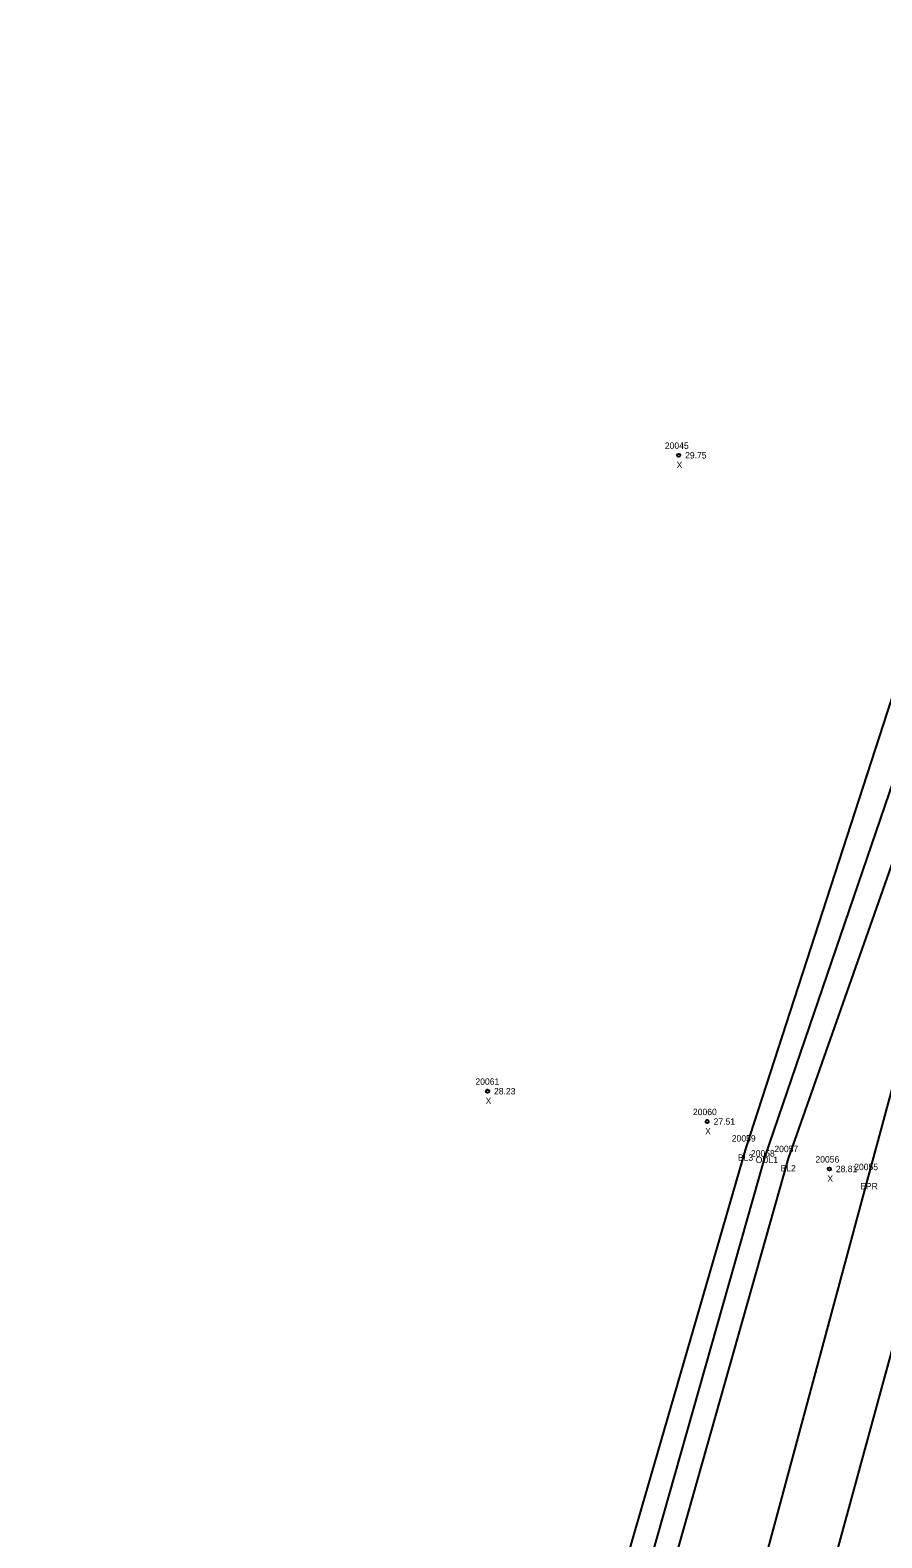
# Model space of a CAD drawing. Extents: x 2432729 to 2433340, y 684958 to 688103.
# Drawn here: x 2432891.8 to 2433024.5, y 687632.9 to 687867.9 of the extents above; entities that cross this region are included whole.
import ezdxf

# ---------------------------------------------------------------- set-up
doc = ezdxf.new("R2010")
doc.units = 0
for name, color, linetype in [('RD_DTM_BkLn1', 7, 'Continuous'), ('RD_EX_H2O', 7, 'Continuous'), ('RD_EX_H2O_txCode', 7, 'Continuous'), ('RD_EX_Road', 7, 'Continuous'), ('RD_EX_Road_txCode', 7, 'Continuous'), ('RD_Sketch8', 7, 'Continuous'), ('RD_SMD_Locator', 7, 'Continuous'), ('RD_SMD_Misc', 7, 'Continuous')]:
    doc.layers.add(name, color=color, linetype=linetype)

msp = doc.modelspace()

# ---------------------------------------------------------------- linework, layer by layer
at = {"layer": 'RD_DTM_BkLn1'}
for points in [[(2433118.26, 688093.2), (2433092.06, 687992.21), (2433063.59, 687892.57), (2433035.4, 687792.67), (2433003.26, 687693.63), (2432973.78, 687591.87), (2432942.45, 687477.63), (2432922.14, 687395), (2432910.39, 687336.67), (2432899.1, 687275.13), (2432892.65, 687218), (2432891.75, 687172.49)], [(2433125.46, 688091.48), (2433098.1, 687989.98), (2433070.67, 687890.07), (2433044.57, 687790.6), (2433009.89, 687691.98), (2432980.82, 687589.28), (2432951.34, 687483.95), (2432927.37, 687394.4), (2432914.6, 687336.1), (2432907.58, 687275.27), (2432904.68, 687217.27), (2432900.37, 687172.96), (2432891.75, 687172.49)], [(2433140.82, 688087.65), (2433112.94, 687984.39), (2433086.23, 687884.97), (2433060.15, 687787.81), (2433032.83, 687687.07), (2433004.93, 687584.9), (2432976.21, 687475.71), (2432953.67, 687387.58), (2432941.78, 687332.31), (2432932.37, 687274.14), (2432926.02, 687213.66), (2432924.35, 687158.94)]]:
    msp.add_lwpolyline(points, dxfattribs=at)
at = {"layer": 'RD_EX_H2O'}
msp.add_lwpolyline([(2433122.48, 688092.22), (2433094.03, 687991.07), (2433066.93, 687892.02), (2433040.1, 687791.41), (2433006.23, 687692.29), (2432977.32, 687590.19), (2432946.52, 687480.52), (2432925.1, 687394.47), (2432912.11, 687336.21), (2432903.51, 687275.66), (2432898.99, 687217.48), (2432895.84, 687179.01)], dxfattribs=at)
at = {"layer": 'RD_EX_Road'}
msp.add_lwpolyline([(2433130.63, 688090.22), (2433103.18, 687988.73), (2433075.68, 687887.89), (2433049.83, 687790.75), (2433022.33, 687689.17), (2432994.76, 687586.82), (2432966.23, 687480.17), (2432943.15, 687390.42), (2432931.4, 687334.3), (2432921.83, 687273.88), (2432915.64, 687215.4), (2432913.86, 687159.12)], dxfattribs=at)
at = {"layer": 'RD_SMD_Locator'}
for centre, radius in [((2432992.82, 687801.62), 0.25), ((2432963.04, 687702.48), 0.25), ((2432997.26, 687697.75), 0.25), ((2433003.26, 687693.63), 0.001), ((2433006.23, 687692.29), 0.001), ((2433009.89, 687691.98), 0.001), ((2433016.31, 687690.36), 0.25), ((2433022.33, 687689.17), 0.001)]:
    msp.add_circle(centre, radius, dxfattribs=at)

# ---------------------------------------------------------------- texts
at = {"layer": 'RD_EX_H2O_txCode'}
for s, p in [('20058', (2433004.07, 687692.29)), ('ODL1', (2433004.82, 687691.29))]:
    msp.add_text(s, height=1, dxfattribs=at).set_placement(p)
at = {"layer": 'RD_EX_Road_txCode'}
for s, p in [('20055', (2433020.17, 687690.17)), ('EPR', (2433021.1, 687687.17))]:
    msp.add_text(s, height=1, dxfattribs=at).set_placement(p)
at = {"layer": 'RD_Sketch8'}
for s, p in [('20045', (2432990.66, 687802.62)), ('X', (2432992.5, 687799.62)), ('29.75', (2432993.82, 687801.12)), ('20061', (2432961.14, 687703.48)), ('28.23', (2432964.04, 687701.98)), ('X', (2432962.73, 687700.48)), ('20060', (2432995.04, 687698.75)), ('27.51', (2432998.26, 687697.25)), ('X', (2432996.94, 687695.75)), ('20056', (2433014.13, 687691.36)), ('28.81', (2433017.31, 687689.86)), ('X', (2433015.99, 687688.36))]:
    msp.add_text(s, height=1, dxfattribs=at).set_placement(p)
at = {"layer": 'RD_SMD_Misc'}
for s, p in [('20059', (2433001.1, 687694.63)), ('BL3', (2433002.05, 687691.63)), ('20057', (2433007.73, 687692.98)), ('BL2', (2433008.69, 687689.98))]:
    msp.add_text(s, height=1, dxfattribs=at).set_placement(p)

doc.saveas('drawing.dxf')
